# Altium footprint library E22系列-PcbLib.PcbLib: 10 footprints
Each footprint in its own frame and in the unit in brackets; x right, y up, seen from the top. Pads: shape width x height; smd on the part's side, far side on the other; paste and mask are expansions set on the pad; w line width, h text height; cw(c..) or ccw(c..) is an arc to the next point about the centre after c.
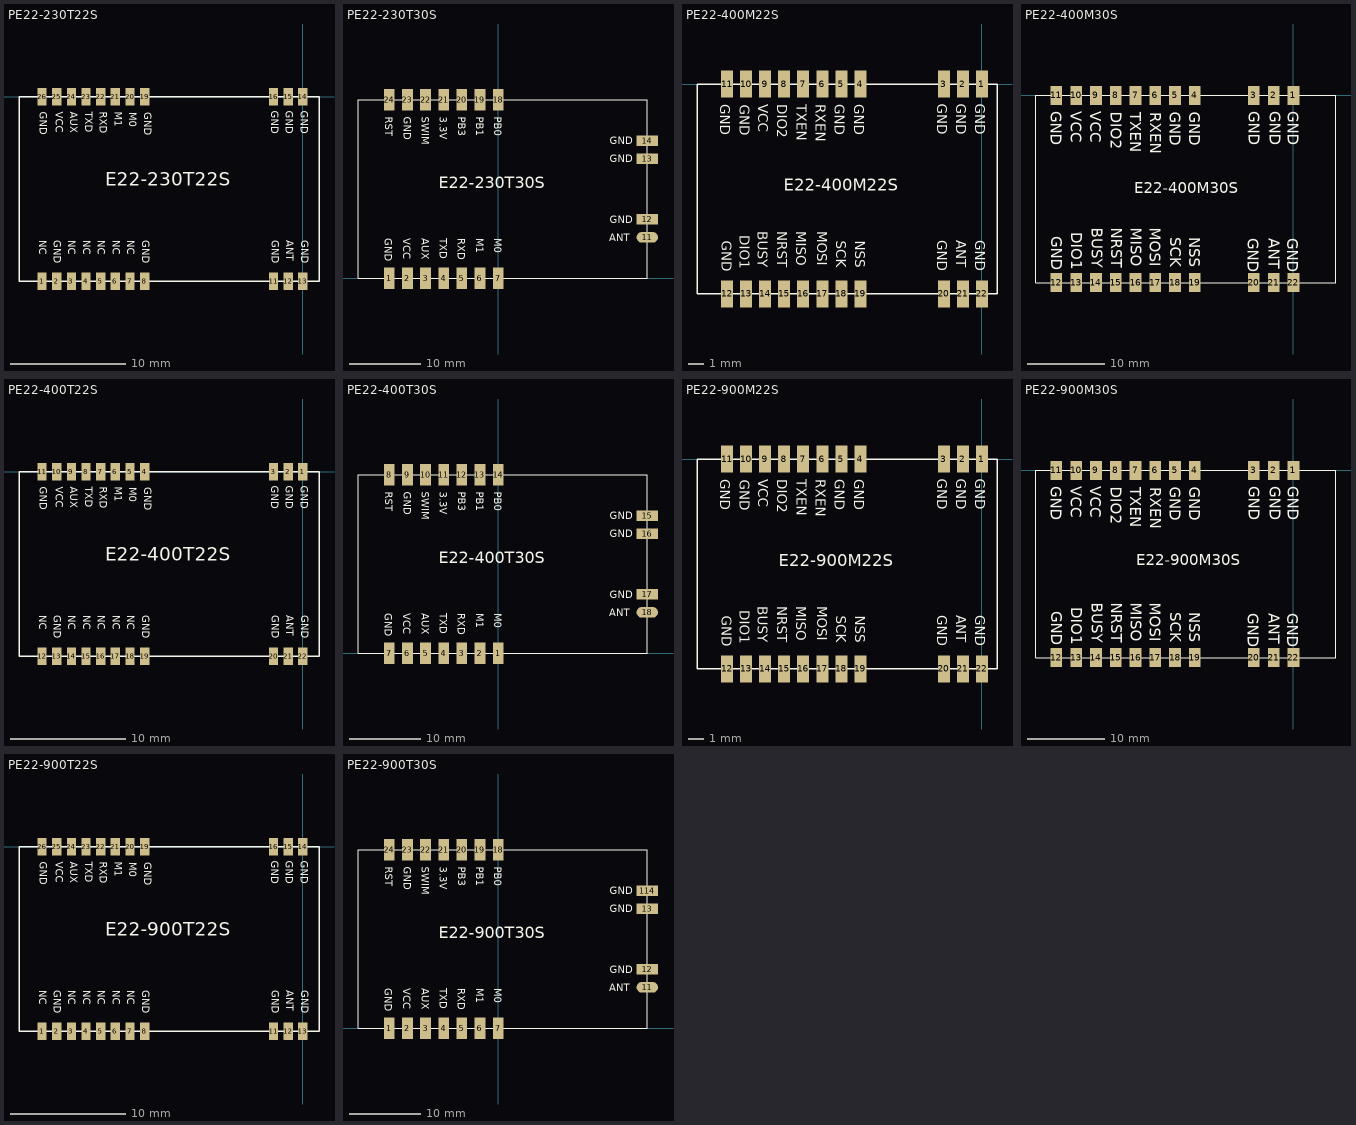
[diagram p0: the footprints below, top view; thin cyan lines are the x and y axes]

## PE22-230T22S [mm] "26mm**16mm*3.23mm-S"
pads (22):
  rect 0.8x1.5 smd: 1(-22.6,-16) 2(-21.33,-16) 3(-20.06,-16) 4(-18.79,-16) 5(-17.52,-16) 6(-16.25,-16) 7(-14.98,-16) 8(-13.71,-16) 11(-2.54,-16) 12(-1.27,-16) 13(0,-16) 14(0,0) 15(-1.27,0) 16(-2.54,0) 19(-13.71,0) 20(-14.98,0) 21(-16.25,0) 22(-17.52,0) 23(-18.79,0) 24(-20.06,0) 25(-21.33,0) 26(-22.6,0)
Top Overlay:
  lines w0.127: -24.6,-16 -24.6,0 1.4,0 1.4,-16 -24.6,-16
  text "GND" at -0.408,-1.224 h1.1
  text "E22-230T22S" at -17.107,-8.126 h2
  text "M0" at -15.257,-1.351 h1.1
  text "M1" at -16.536,-1.301 h1.1
  text "RXD" at -17.814,-1.301 h1.1
  text "TXD" at -19.093,-1.301 h1.1
  text "AUX" at -20.372,-1.301 h1.1
  text "VCC" at -21.651,-1.301 h1.1
  text "GND" at -23.01,-1.301 h1.1
  text "GND" at -13.97,-1.351 h1.1
  text "NC" at -23.06,-12.441 h1.1
  text "GND" at -21.811,-12.441 h1.1
  text "NC" at -20.532,-12.441 h1.1
  text "NC" at -19.253,-12.441 h1.1
  text "NC" at -17.974,-12.441 h1.1
  text "NC" at -16.696,-12.441 h1.1
  text "NC" at -15.417,-12.441 h1.1
  text "GND" at -14.138,-12.441 h1.1
  text "GND" at -0.358,-12.441 h1.1
  text "ANT" at -1.637,-12.441 h1.1
  text "GND" at -2.916,-12.441 h1.1
  text "GND" at -2.966,-1.224 h1.1
  text "GND" at -1.687,-1.224 h1.1

## PE22-230T30S [mm] "40.5mm*25mm*3.80mm-S"
pads (18):
  rect 1.5x3 smd: 1(-15.24,0) 2(-12.7,0) 3(-10.16,0) 4(-7.62,0) 5(-5.08,0) 6(-2.54,0) 7(0,0) 18(0,25) 19(-2.54,25) 20(-5.08,25) 21(-7.62,25) 22(-10.16,25) 23(-12.7,25) 24(-15.24,25)
  oval 3x1.5 smd: 11(20.88,5.73)
  rect 3x1.5 smd: 12(20.88,8.27) 13(20.88,16.73) 14(20.88,19.27)
Top Overlay:
  lines w0.127: -19.62,0 20.88,0 20.88,25 -19.62,25 -19.62,0
  text "SWIM" at -10.73,22.606 h1
  text "GND" at 15.602,18.73 h1
  text "GND" at 15.602,16.22 h1
  text "PB0" at -0.557,22.592 h1
  text "PB1" at -3.067,22.592 h1
  text "PB3" at -5.617,22.592 h1
  text "3.3V" at -8.147,22.592 h1
  text "GND" at -13.237,22.592 h1
  text "RST" at -15.827,22.592 h1
  text "GND" at -15.847,5.575 h1
  text "VCC" at -13.257,5.575 h1
  text "AUX" at -10.707,5.575 h1
  text "TXD" at -8.167,5.575 h1
  text "RXD" at -5.637,5.575 h1
  text "M1" at -3.087,5.575 h1
  text "M0" at -0.577,5.575 h1
  text "ANT" at 15.554,5.17 h1
  text "GND" at 15.602,7.72 h1
  text "E22-230T30S" at -8.317,12.065 h2.8

## PE22-400M22S [mm] "20mm*14mm*2.8mm-S"
pads (22):
  rect 0.8x1.8 smd: 1(0,0) 2(-1.27,0) 3(-2.54,0) 4(-8.11,0) 5(-9.38,0) 6(-10.65,0) 7(-11.92,0) 8(-13.19,0) 9(-14.46,0) 10(-15.73,0) 11(-17,0) 12(-17,-14) 13(-15.73,-14) 14(-14.46,-14) 15(-13.19,-14) 16(-11.92,-14) 17(-10.65,-14) 18(-9.38,-14) 19(-8.11,-14) 20(-2.54,-14) 21(-1.27,-14) 22(0,-14)
Top Overlay:
  lines w0.1: -19,-14 -19,0 1,0 1,-14 -19,-14
  text "GND" at -8.528,-1.353 h0.65
  text "GND" at -9.807,-1.353 h0.65
  text "RXEN" at -11.086,-1.353 h0.65
  text "TXEN" at -12.364,-1.353 h0.65
  text "DIO2" at -13.643,-1.353 h0.65
  text "VCC" at -14.922,-1.353 h0.65
  text "GND" at -16.14,-1.373 h0.65
  text "GND" at -17.45,-1.353 h0.65
  text "GND" at -2.996,-1.323 h0.65
  text "GND" at -1.717,-1.323 h0.65
  text "GND" at -0.438,-1.323 h0.65
  text "GND" at -0.438,-10.428 h0.65
  text "ANT" at -1.717,-10.428 h0.65
  text "GND" at -2.996,-10.428 h0.65
  text "GND" at -17.349,-10.444 h0.65
  text "DIO1" at -16.14,-10.097 h0.65
  text "BUSY" at -14.936,-9.809 h0.65
  text "NRST" at -13.666,-9.809 h0.65
  text "MISO" at -12.396,-9.809 h0.65
  text "MOSI" at -10.999,-9.809 h0.65
  text "SCK" at -9.729,-10.444 h0.65
  text "NSS" at -8.459,-10.444 h0.65
  text "E22-400M22S" at -13.208,-7.112 h0.8

## PE22-400M30S [mm] "38.5mm*24mm*3.8mm-S"
pads (22):
  rect 1.5x2.5 smd: 1(0,0) 2(-2.54,0) 3(-5.08,0) 4(-12.65,0) 5(-15.19,0) 6(-17.73,0) 7(-20.27,0) 8(-22.81,0) 9(-25.35,0) 10(-27.89,0) 11(-30.43,0) 12(-30.43,-24) 13(-27.89,-24) 14(-25.35,-24) 15(-22.81,-24) 16(-20.27,-24) 17(-17.73,-24) 18(-15.19,-24) 19(-12.65,-24) 20(-5.08,-24) 21(-2.54,-24) 22(0,-24)
Top Overlay:
  lines w0.1: -33.04,-24 -33.04,0 5.46,0 5.46,-24 -33.04,-24
  text "NSS" at -13.351,-18.17 h1.4
  text "SCK" at -15.816,-18.17 h1.4
  text "MOSI" at -18.416,-16.979 h1.4
  text "MISO" at -20.881,-16.979 h1.4
  text "NRST" at -23.406,-16.979 h1.4
  text "BUSY" at -25.871,-16.979 h1.4
  text "DIO1" at -28.532,-17.552 h1.4
  text "GND" at -31.079,-18.064 h1.4
  text "GND" at -5.844,-18.291 h1.4
  text "ANT" at -3.202,-18.291 h1.4
  text "GND" at -0.775,-18.291 h1.4
  text "GND" at -0.748,-1.991 h1.4
  text "GND" at -3.07,-1.991 h1.4
  text "GND" at -5.743,-1.991 h1.4
  text "GND" at -31.143,-2.051 h1.4
  text "VCC" at -28.61,-2.051 h1.4
  text "VCC" at -26.076,-2.051 h1.4
  text "DIO2" at -23.438,-2.117 h1.4
  text "TXEN" at -20.935,-2.169 h1.4
  text "RXEN" at -18.402,-2.169 h1.4
  text "GND" at -15.899,-2.096 h1.4
  text "GND" at -13.366,-2.096 h1.4
  text "E22-400M30S" at -20.447,-12.573 h1.4

## PE22-400T22S [mm] "26mm**16mm*3.23mm-S"
pads (22):
  rect 0.8x1.5 smd: 1(0,0) 2(-1.27,0) 3(-2.54,0) 4(-13.71,0) 5(-14.98,0) 6(-16.25,0) 7(-17.52,0) 8(-18.79,0) 9(-20.06,0) 10(-21.33,0) 11(-22.6,0) 12(-22.6,-16) 13(-21.33,-16) 14(-20.06,-16) 15(-18.79,-16) 16(-17.52,-16) 17(-16.25,-16) 18(-14.98,-16) 19(-13.71,-16) 20(-2.54,-16) 21(-1.27,-16) 22(0,-16)
Top Overlay:
  lines w0.127: -24.6,-16 1.4,-16 1.4,0 -24.6,0 -24.6,-16
  text "GND" at -1.687,-1.224 h1.1
  text "GND" at -2.966,-1.224 h1.1
  text "GND" at -2.916,-12.441 h1.1
  text "ANT" at -1.637,-12.441 h1.1
  text "GND" at -0.358,-12.441 h1.1
  text "GND" at -14.138,-12.441 h1.1
  text "NC" at -15.417,-12.441 h1.1
  text "NC" at -16.696,-12.441 h1.1
  text "NC" at -17.974,-12.441 h1.1
  text "NC" at -19.253,-12.441 h1.1
  text "NC" at -20.532,-12.441 h1.1
  text "GND" at -21.811,-12.441 h1.1
  text "NC" at -23.06,-12.441 h1.1
  text "GND" at -13.97,-1.351 h1.1
  text "GND" at -23.01,-1.301 h1.1
  text "VCC" at -21.651,-1.301 h1.1
  text "AUX" at -20.372,-1.301 h1.1
  text "TXD" at -19.093,-1.301 h1.1
  text "RXD" at -17.814,-1.301 h1.1
  text "M1" at -16.536,-1.301 h1.1
  text "M0" at -15.257,-1.351 h1.1
  text "E22-400T22S" at -17.107,-8.126 h2
  text "GND" at -0.408,-1.224 h1.1

## PE22-400T30S [mm] "40.5mm*25mm*3.80mm-S"
pads (18):
  rect 1.5x3 smd: 1(0,0) 2(-2.54,0) 3(-5.08,0) 4(-7.62,0) 5(-10.16,0) 6(-12.7,0) 7(-15.24,0) 8(-15.24,25) 9(-12.7,25) 10(-10.16,25) 11(-7.62,25) 12(-5.08,25) 13(-2.54,25) 14(0,25)
  rect 3x1.5 smd: 15(20.88,19.27) 16(20.88,16.73) 17(20.88,8.27)
  oval 3x1.5 smd: 18(20.88,5.73)
Top Overlay:
  lines w0.127: -19.62,0 -19.62,25 20.88,25 20.88,0 -19.62,0
  text "E22-400T30S" at -8.317,12.065 h2.8
  text "GND" at 15.602,7.72 h1
  text "ANT" at 15.554,5.17 h1
  text "M0" at -0.577,5.575 h1
  text "M1" at -3.087,5.575 h1
  text "RXD" at -5.637,5.575 h1
  text "TXD" at -8.167,5.575 h1
  text "AUX" at -10.707,5.575 h1
  text "VCC" at -13.257,5.575 h1
  text "GND" at -15.847,5.575 h1
  text "RST" at -15.827,22.592 h1
  text "GND" at -13.237,22.592 h1
  text "3.3V" at -8.147,22.592 h1
  text "PB3" at -5.617,22.592 h1
  text "PB1" at -3.067,22.592 h1
  text "PB0" at -0.557,22.592 h1
  text "GND" at 15.602,16.22 h1
  text "GND" at 15.602,18.73 h1
  text "SWIM" at -10.73,22.606 h1

## PE22-900M22S [mm] "20mm*14mm*2.8mm-S"
pads (22):
  rect 0.8x1.8 smd: 1(0,0) 2(-1.27,0) 3(-2.54,0) 4(-8.11,0) 5(-9.38,0) 6(-10.65,0) 7(-11.92,0) 8(-13.19,0) 9(-14.46,0) 10(-15.73,0) 11(-17,0) 12(-17,-14) 13(-15.73,-14) 14(-14.46,-14) 15(-13.19,-14) 16(-11.92,-14) 17(-10.65,-14) 18(-9.38,-14) 19(-8.11,-14) 20(-2.54,-14) 21(-1.27,-14) 22(0,-14)
Top Overlay:
  lines w0.1: -19,-14 -19,0 1,0 1,-14 -19,-14
  text "GND" at -8.528,-1.353 h0.65
  text "GND" at -9.807,-1.353 h0.65
  text "RXEN" at -11.086,-1.353 h0.65
  text "TXEN" at -12.364,-1.353 h0.65
  text "DIO2" at -13.643,-1.353 h0.65
  text "VCC" at -14.922,-1.353 h0.65
  text "GND" at -16.14,-1.373 h0.65
  text "GND" at -17.45,-1.353 h0.65
  text "GND" at -2.996,-1.323 h0.65
  text "GND" at -1.717,-1.323 h0.65
  text "GND" at -0.438,-1.323 h0.65
  text "GND" at -0.438,-10.428 h0.65
  text "ANT" at -1.717,-10.428 h0.65
  text "GND" at -2.996,-10.428 h0.65
  text "GND" at -17.349,-10.444 h0.65
  text "DIO1" at -16.14,-10.097 h0.65
  text "BUSY" at -14.936,-9.809 h0.65
  text "NRST" at -13.666,-9.809 h0.65
  text "MISO" at -12.396,-9.809 h0.65
  text "MOSI" at -10.999,-9.809 h0.65
  text "SCK" at -9.729,-10.444 h0.65
  text "NSS" at -8.459,-10.444 h0.65
  text "E22-900M22S" at -13.539,-7.142 h0.8

## PE22-900M30S [mm] "38.5mm*24mm*3.8mm-S"
pads (22):
  rect 1.5x2.5 smd: 1(0,0) 2(-2.54,0) 3(-5.08,0) 4(-12.65,0) 5(-15.19,0) 6(-17.73,0) 7(-20.27,0) 8(-22.81,0) 9(-25.35,0) 10(-27.89,0) 11(-30.43,0) 12(-30.43,-24) 13(-27.89,-24) 14(-25.35,-24) 15(-22.81,-24) 16(-20.27,-24) 17(-17.73,-24) 18(-15.19,-24) 19(-12.65,-24) 20(-5.08,-24) 21(-2.54,-24) 22(0,-24)
Top Overlay:
  lines w0.1: -33.04,-24 -33.04,0 5.46,0 5.46,-24 -33.04,-24
  text "NSS" at -13.351,-18.17 h1.4
  text "SCK" at -15.816,-18.17 h1.4
  text "MOSI" at -18.416,-16.979 h1.4
  text "MISO" at -20.881,-16.979 h1.4
  text "NRST" at -23.406,-16.979 h1.4
  text "BUSY" at -25.871,-16.979 h1.4
  text "DIO1" at -28.532,-17.552 h1.4
  text "GND" at -31.079,-18.064 h1.4
  text "GND" at -5.844,-18.291 h1.4
  text "ANT" at -3.202,-18.291 h1.4
  text "GND" at -0.775,-18.291 h1.4
  text "GND" at -0.748,-1.991 h1.4
  text "GND" at -3.07,-1.991 h1.4
  text "GND" at -5.743,-1.991 h1.4
  text "GND" at -31.143,-2.051 h1.4
  text "VCC" at -28.61,-2.051 h1.4
  text "VCC" at -26.076,-2.051 h1.4
  text "DIO2" at -23.438,-2.117 h1.4
  text "TXEN" at -20.935,-2.169 h1.4
  text "RXEN" at -18.402,-2.169 h1.4
  text "GND" at -15.899,-2.096 h1.4
  text "GND" at -13.366,-2.096 h1.4
  text "E22-900M30S" at -20.193,-12.192 h1.4

## PE22-900T22S [mm] "26mm**16mm*3.23mm-S"
pads (22):
  rect 0.8x1.5 smd: 1(-22.6,-16) 2(-21.33,-16) 3(-20.06,-16) 4(-18.79,-16) 5(-17.52,-16) 6(-16.25,-16) 7(-14.98,-16) 8(-13.71,-16) 11(-2.54,-16) 12(-1.27,-16) 13(0,-16) 14(0,0) 15(-1.27,0) 16(-2.54,0) 19(-13.71,0) 20(-14.98,0) 21(-16.25,0) 22(-17.52,0) 23(-18.79,0) 24(-20.06,0) 25(-21.33,0) 26(-22.6,0)
Top Overlay:
  lines w0.127: -24.6,-16 -24.6,0 1.4,0 1.4,-16 -24.6,-16
  text "GND" at -0.408,-1.224 h1.1
  text "E22-900T22S" at -17.107,-8.126 h2
  text "M0" at -15.257,-1.351 h1.1
  text "M1" at -16.536,-1.301 h1.1
  text "RXD" at -17.814,-1.301 h1.1
  text "TXD" at -19.093,-1.301 h1.1
  text "AUX" at -20.372,-1.301 h1.1
  text "VCC" at -21.651,-1.301 h1.1
  text "GND" at -23.01,-1.301 h1.1
  text "GND" at -13.97,-1.351 h1.1
  text "NC" at -23.06,-12.441 h1.1
  text "GND" at -21.811,-12.441 h1.1
  text "NC" at -20.532,-12.441 h1.1
  text "NC" at -19.253,-12.441 h1.1
  text "NC" at -17.974,-12.441 h1.1
  text "NC" at -16.696,-12.441 h1.1
  text "NC" at -15.417,-12.441 h1.1
  text "GND" at -14.138,-12.441 h1.1
  text "GND" at -0.358,-12.441 h1.1
  text "ANT" at -1.637,-12.441 h1.1
  text "GND" at -2.916,-12.441 h1.1
  text "GND" at -2.966,-1.224 h1.1
  text "GND" at -1.687,-1.224 h1.1

## PE22-900T30S [mm] "40.5mm*25mm*3.80mm-S"
pads (18):
  rect 1.5x3 smd: 1(-15.24,0) 2(-12.7,0) 3(-10.16,0) 4(-7.62,0) 5(-5.08,0) 6(-2.54,0) 7(0,0) 18(0,25) 19(-2.54,25) 20(-5.08,25) 21(-7.62,25) 22(-10.16,25) 23(-12.7,25) 24(-15.24,25)
  oval 3x1.5 smd: 11(20.88,5.73)
  rect 3x1.5 smd: 12(20.88,8.27) 13(20.88,16.73) 114(20.88,19.27)
Top Overlay:
  lines w0.127: -19.62,0 -19.62,25 20.88,25 20.88,0 -19.62,0
  text "E22-900T30S" at -8.317,12.065 h2.8
  text "GND" at 15.602,7.72 h1
  text "ANT" at 15.554,5.17 h1
  text "M0" at -0.577,5.575 h1
  text "M1" at -3.087,5.575 h1
  text "RXD" at -5.637,5.575 h1
  text "TXD" at -8.167,5.575 h1
  text "AUX" at -10.707,5.575 h1
  text "VCC" at -13.257,5.575 h1
  text "GND" at -15.847,5.575 h1
  text "RST" at -15.827,22.592 h1
  text "GND" at -13.237,22.592 h1
  text "3.3V" at -8.147,22.592 h1
  text "PB3" at -5.617,22.592 h1
  text "PB1" at -3.067,22.592 h1
  text "PB0" at -0.557,22.592 h1
  text "GND" at 15.602,16.22 h1
  text "GND" at 15.602,18.73 h1
  text "SWIM" at -10.73,22.606 h1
